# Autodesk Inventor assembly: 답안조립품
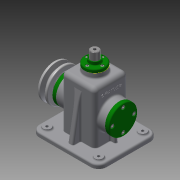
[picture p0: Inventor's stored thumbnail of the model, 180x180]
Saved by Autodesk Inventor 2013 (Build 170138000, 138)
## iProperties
Created: 2016-01
Part Number: 답안조립품
Document SubType Name: Assembly
Designer: Administrator
Author: Administrator
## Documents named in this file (19)
- C:\Users\Administrator\Desktop\460127V1017\답안조립품.iam
- C:\Users\Administrator\Desktop\460127V1017\본체1.ipt
- C:\Users\Administrator\Desktop\460127V1017\V-벨트풀리.ipt
- C:\Users\Administrator\Desktop\460127V1017\고정핀.ipt
- C:\Users\Administrator\Desktop\460127V1017\뒤커버.ipt
- C:\Users\Administrator\Desktop\460127V1017\링크.ipt
- C:\Users\Administrator\Desktop\460127V1017\멈춤링 6 x 5.ipt
- C:\Users\Administrator\Desktop\460127V1017\멈춤링 15 x 1.ipt
- C:\Users\Administrator\Desktop\460127V1017\베어링 15 x 35 x 11.ipt
- C:\Users\Administrator\Desktop\460127V1017\볼트 M3 x 8.ipt
- C:\Users\Administrator\Desktop\460127V1017\볼트 M4 x 10.ipt
- C:\Users\Administrator\Desktop\460127V1017\볼트 M6 x 12.ipt
- C:\Users\Administrator\Desktop\460127V1017\상부부시.ipt
- C:\Users\Administrator\Desktop\460127V1017\슬라이드바.ipt
- C:\Users\Administrator\Desktop\460127V1017\앞커버.ipt
- C:\Users\Administrator\Desktop\460127V1017\오일실 15 25 7.ipt
- C:\Users\Administrator\Desktop\460127V1017\와셔.ipt
- C:\Users\Administrator\Desktop\460127V1017\키 5 x 5 x 14.ipt
- C:\Users\Administrator\Desktop\460127V1017\편심축.ipt
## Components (15 placed, 5 different names)
1. V-벨트풀리:1 — 각도:2
2. 고정핀:1
3. ISO 4018 M6 x 12:1
4. ISO 4762 M4 x 10:1
5. ISO 4762 M4 x 10:3
6. ISO 4762 M4 x 10:4
7. ISO 4762 M4 x 10:5
8. ISO 4762 M4 x 10:2
9. ISO 4762 M4 x 10:6
10. ISO 4762 M4 x 10:7
11. ISO 4762 M4 x 10:8
12. ISO 4762 M3 x 8:1
13. ISO 4762 M3 x 8:2
14. ISO 4762 M3 x 8:3
15. ISO 4762 M3 x 8:4
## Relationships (1: Angle 1)
- 각도:2 [Angle]: V-벨트풀리:1
